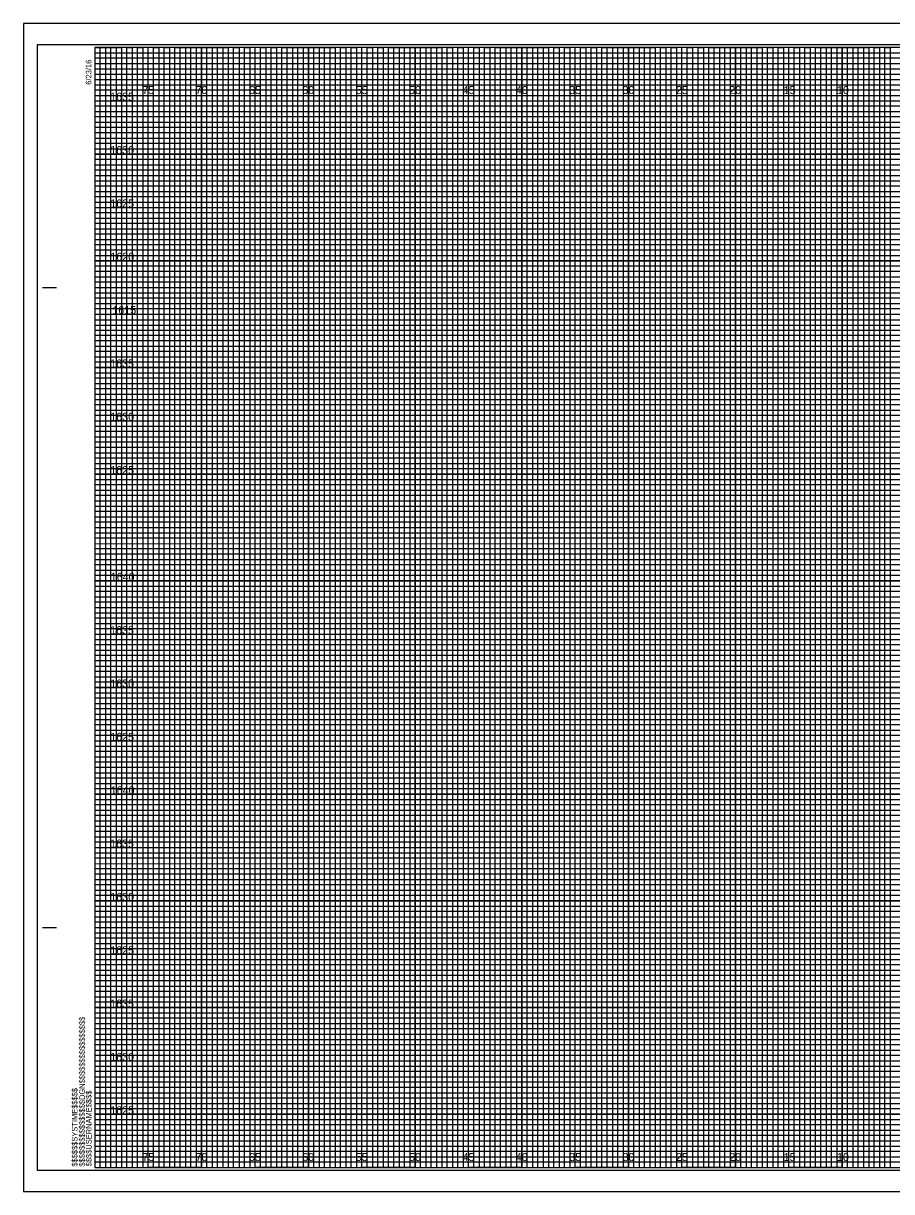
# Model space of a CAD drawing. Extents: x -7 to 162, y -2 to 107.
# Drawn here: x -6.7 to 74.6, y -2.3 to 107.3 of the extents above; entities that cross this region are included whole.
import ezdxf

# ---------------------------------------------------------------- set-up
doc = ezdxf.new("R2010")
doc.units = 0
for name, color, linetype in [('Prop XS Elevation Labels', 7, 'Continuous'), ('Prop XS Offset Labels', 7, 'Continuous'), ('Sheet Cross Section CELL', 7, 'Continuous'), ('Sheet Cross Section Grid Major CELL', 7, 'Continuous'), ('Sheet Cross Section Grid Middle CELL', 7, 'Continuous'), ('Sheet Cross Section Grid Minor 1 CELL', 7, 'Continuous'), ('Sheet Cross Section Grid Minor 2 CELL', 7, 'Continuous'), ('Sheet Cutting Line CELL', 7, 'Continuous'), ('Sheet DOT Grid CELL', 7, 'Continuous'), ('Sheet Plot Border Inside CELL', 7, 'Continuous'), ('Sheet Plot Border Outside CELL', 7, 'Continuous')]:
    doc.layers.add(name, color=color, linetype=linetype)

msp = doc.modelspace()

# ---------------------------------------------------------------- linework, layer by layer
at = {"layer": 'Sheet Cross Section CELL'}
for p, q in [((-4.9, 82.5), (-3.65, 82.5)), ((-4.85, 82.5), (-3.6, 82.5)), ((-4.9, 22.5), (-3.65, 22.5)), ((-4.85, 22.5), (-3.6, 22.5)), ((0, 0), (0, 0)), ((0, 0), (0, 0)), ((0, 0), (0, 0)), ((0, 0), (0, 0)), ((0, 0), (0, 0)), ((0, 0), (0, 0)), ((0, 0), (0, 0))]:
    msp.add_line(p, q, dxfattribs=at)
msp.add_lwpolyline([(160, 105), (0, 105), (0, 0), (160, 0)], close=True, dxfattribs=at)
at = {"layer": 'Sheet Cross Section Grid Major CELL'}
for p, q in [((5, 105), (0, 105)), ((5, 0), (5, 105)), ((15, 105), (10, 105)), ((10, 105), (10, 0)), ((15, 0), (15, 105)), ((25, 105), (20, 105)), ((20, 105), (20, 0)), ((25, 0), (25, 105)), ((35, 105), (30, 105)), ((30, 105), (30, 0)), ((35, 0), (35, 105)), ((45, 105), (40, 105)), ((40, 105), (40, 0)), ((45, 0), (45, 105)), ((55, 105), (50, 105)), ((50, 105), (50, 0)), ((55, 0), (55, 105)), ((65, 105), (60, 105)), ((60, 105), (60, 0)), ((65, 0), (65, 105)), ((75, 105), (70, 105)), ((70, 105), (70, 0)), ((10, 0), (5, 0)), ((20, 0), (15, 0)), ((30, 0), (25, 0)), ((40, 0), (35, 0)), ((50, 0), (45, 0)), ((60, 0), (55, 0)), ((70, 0), (65, 0))]:
    msp.add_line(p, q, dxfattribs=at)
for points in [[(0, 100), (160, 100), (160, 95), (0, 95)], [(0, 90), (160, 90), (160, 85), (0, 85)], [(0, 80), (160, 80), (160, 75), (0, 75)], [(0, 70), (160, 70), (160, 65), (0, 65)], [(0, 60), (160, 60), (160, 55), (0, 55)], [(0, 50), (160, 50), (160, 45), (0, 45)], [(0, 40), (160, 40), (160, 35), (0, 35)], [(0, 30), (160, 30), (160, 25), (0, 25)], [(0, 20), (160, 20), (160, 15), (0, 15)], [(0, 10), (160, 10), (160, 5), (0, 5)]]:
    msp.add_lwpolyline(points, dxfattribs=at)
at = {"layer": 'Sheet Cross Section Grid Middle CELL'}
for points in [[(0, 105), (2.5, 105), (2.5, 0), (7.5, 0), (7.5, 105), (12.5, 105), (12.5, 0), (17.5, 0), (17.5, 105), (22.5, 105), (22.5, 0), (27.5, 0), (27.5, 105), (32.5, 105), (32.5, 0), (37.5, 0), (37.5, 105), (42.5, 105), (42.5, 0), (47.5, 0), (47.5, 105), (52.5, 105), (52.5, 0), (57.5, 0), (57.5, 105), (62.5, 105), (62.5, 0), (67.5, 0), (67.5, 105), (72.5, 105), (72.5, 0), (77.5, 0)], [(0, 102.5), (137.5, 102.5)], [(0, 92.5), (160, 92.5), (160, 97.5), (0, 97.5)], [(0, 82.5), (160, 82.5), (160, 87.5), (0, 87.5)], [(0, 72.5), (160, 72.5), (160, 77.5), (0, 77.5)], [(0, 62.5), (160, 62.5), (160, 67.5), (0, 67.5)], [(0, 52.5), (160, 52.5), (160, 57.5), (0, 57.5)], [(0, 42.5), (160, 42.5), (160, 47.5), (0, 47.5)], [(0, 32.5), (160, 32.5), (160, 37.5), (0, 37.5)], [(0, 22.5), (160, 22.5), (160, 27.5), (0, 27.5)], [(0, 12.5), (160, 12.5), (160, 17.5), (0, 17.5)], [(0, 2.5), (160, 2.5), (160, 7.5), (0, 7.5)]]:
    msp.add_lwpolyline(points, dxfattribs=at)
at = {"layer": 'Sheet Cross Section Grid Minor 1 CELL'}
for p, q in [((0, 104.5), (130, 104.5)), ((130, 103.99), (0, 103.99)), ((0, 103.99), (0, 103.5)), ((0, 103.5), (130, 103.5)), ((130, 102.95), (0, 102.95)), ((0, 102.95), (0, 102)), ((0, 102), (160, 102))]:
    msp.add_line(p, q, dxfattribs=at)
for points in [[(0, 101.5), (135, 101.5), (160, 101.5), (160, 101), (0, 101)], [(0, 100.5), (160, 100.5), (160, 99.5), (0, 99.5)], [(0, 99), (160, 99), (160, 98.5), (0, 98.49)], [(0, 98), (160, 98), (160, 97), (0, 97)], [(0, 96.5), (160, 96.5), (160, 96), (0, 96)], [(0, 95.5), (160, 95.5), (160, 94.5), (0, 94.5)], [(0, 94), (160, 94), (160, 93.5), (0, 93.5)], [(0, 93), (160, 93), (160, 92), (0, 92)], [(0, 91.5), (160, 91.5), (160, 91), (0, 91)], [(0, 90.5), (160, 90.5), (160, 89.5), (0, 89.5)], [(0, 89), (160, 89), (160, 88.5), (0, 88.5)], [(0, 88), (160, 88), (160, 86.98), (160, 86.5), (160, 86), (0, 86)], [(0, 87), (160, 87), (160, 86.5), (0, 86.5)], [(0, 85.5), (160, 85.5), (160, 84.5), (0, 84.52)], [(0, 84.52), (160, 84.5), (160, 84), (0, 84)], [(0, 83.5), (160, 83.5), (160, 83), (0, 83)], [(0, 82), (160, 82), (160, 81.5), (0, 81.5)], [(0, 81), (160, 81), (160, 80.5), (0, 80.5)], [(-0.04, 79.45), (160, 79.45), (160, 78.94), (-0.04, 78.94)], [(0, 78.5), (160, 78.5), (160, 78), (0, 78)], [(0, 77), (160, 77), (160, 76.5), (0, 76.5)], [(0, 76), (160, 76), (160, 75.5), (0, 75.5)], [(0, 74.5), (160, 74.5), (160, 74), (0, 74)], [(0, 73.5), (160, 73.5), (160, 73), (0, 73)], [(0, 72), (160, 72), (160, 71.5), (0, 71.5)], [(0, 71), (160, 71), (160, 70.5), (0, 70.5)], [(0, 69.5), (160, 69.5), (160, 68.99), (0, 69)], [(0, 68.5), (160, 68.5), (160, 68), (0, 68)], [(0, 67), (160, 67), (160, 66.5), (0, 66.5)], [(0, 66), (160, 66), (160, 65.5), (0, 65.5)], [(0, 64.5), (160, 64.5), (160, 64), (0, 64)], [(0, 63.5), (160, 63.5), (160, 63), (0, 63)], [(0, 62), (160, 62), (160, 61.5), (0, 61.5)], [(0, 61), (160, 61), (160, 60.5), (0, 60.5)], [(0, 59.5), (160, 59.5), (160, 59), (0, 59)], [(0, 58.5), (160.03, 58.45), (160, 58), (0, 58)], [(0, 57), (160, 57), (160, 56.5), (0, 56.5)], [(0, 56), (160, 56), (160, 55.5), (0, 55.5)], [(0, 54.5), (160, 54.5), (160, 54), (0, 54)], [(0, 53.5), (160, 53.5), (160, 53), (0, 53)], [(0, 52), (160, 52), (160, 51.5), (0, 51.5)], [(0, 51), (160, 51), (160, 50.5), (0, 50.5)], [(0, 49.5), (160, 49.5), (160, 49), (0, 49)], [(0, 48.5), (160, 48.5), (160, 48), (0, 48)], [(0, 47), (160, 47), (160, 46.5), (0, 46.5)], [(0, 46), (160, 46), (160, 45.5), (0, 45.5)], [(0, 44.5), (160, 44.5), (160, 44), (0, 44)], [(0, 43.5), (160, 43.5), (160, 43), (0, 43)], [(0, 42), (160, 42), (160, 41.5), (0, 41.5)], [(0, 41), (160, 41), (160, 40.5), (0, 40.5)], [(0, 39.5), (160, 39.5), (160, 38.99), (0, 39)], [(0, 38.5), (160, 38.5), (160, 38), (0, 38)], [(0, 37), (160, 37), (160, 36.5), (0, 36.5)], [(0, 36), (160, 36), (160, 35.5), (0, 35.5)], [(0, 34.5), (160, 34.5), (160, 34), (0, 34)], [(0, 33.5), (160, 33.5), (160, 33), (0, 33)], [(0, 32), (160, 32), (160, 31.5), (0, 31.5)], [(0, 31), (160, 31), (160, 30.5), (0, 30.5)], [(0, 29.5), (160, 29.5), (160, 29), (0, 29)], [(0, 28.5), (160.03, 28.46), (160, 28), (0, 28)], [(0, 27), (160, 27), (160, 26.5), (0, 26.5)], [(0, 26), (160, 26), (160, 25.5), (0, 25.5)], [(0, 24.5), (160, 24.5), (160, 24), (0, 24)], [(0, 23.5), (160, 23.5), (160, 23), (0, 23)], [(0, 22), (160, 22), (160, 21.5), (0, 21.5)], [(0, 21), (160, 21), (160, 20.5), (0, 20.5)], [(0, 19.5), (160, 19.5), (160, 19), (0, 19)], [(0, 18.5), (160, 18.5), (160, 18), (0, 18)], [(0, 17), (160, 17), (160, 16.5), (0, 16.5)], [(0, 16), (160, 16), (160, 15.5), (0, 15.5)], [(0, 14.5), (160, 14.5), (160, 14), (0, 14)], [(0, 13.5), (160, 13.5), (160, 13), (0, 13)], [(0, 12), (160, 12), (160, 11.5), (0, 11.5)], [(0, 11), (160, 11), (160, 10.5), (0, 10.5)], [(0, 9.5), (160, 9.5), (160, 9), (0, 9)], [(0, 8.5), (160, 8.5), (160, 8), (0, 8)], [(0, 7), (160, 7), (160, 6.5), (0, 6.5)], [(0, 6), (160, 6), (160, 5.5), (0, 5.5)], [(0, 4.5), (160, 4.5), (160, 4), (0, 4)], [(0, 3.5), (160, 3.5), (160, 3), (0, 3)], [(0, 2), (160, 2), (160, 1.5), (0, 1.5)], [(0, 1), (160, 1), (160, 0.5), (0, 0.5)]]:
    msp.add_lwpolyline(points, dxfattribs=at)
at = {"layer": 'Sheet Cross Section Grid Minor 2 CELL'}
for points in [[(0, 0), (0.5, 0), (0.5, 105), (1, 105), (1, 0)], [(1, 0), (1.5, 0), (1.5, 105), (2, 105), (2, 0)], [(2.5, 0), (3, 0), (3, 105), (3.5, 105), (3.5, 0)], [(3.5, 0), (4, 0), (4, 105), (4.5, 105), (4.5, 0)], [(5, 0), (5.5, 0), (5.5, 105), (6, 105), (6, 0)], [(6, 0), (6.5, 0), (6.5, 105), (7, 105), (7, 0)], [(7.5, 0), (8, 0), (8, 105), (8.5, 105), (8.5, 0)], [(8.5, 0), (9, 0), (9, 105), (9.5, 105), (9.5, 0)], [(10, 0), (10.5, 0), (10.5, 105), (11, 105), (11, 0)], [(11, 0), (11.5, 0), (11.5, 105), (12, 105), (12, 0)], [(12.5, 0), (13, 0), (13, 105), (13.5, 105), (13.5, 0)], [(13.5, 0), (14, 0), (14, 105), (14.5, 105), (14.5, 0)], [(15, 0), (15.5, 0), (15.5, 105), (16, 105), (16, 0)], [(16, 0), (16.5, 0), (16.5, 105), (17, 105), (17, 0)], [(17.5, 0), (18, 0), (18, 105), (18.5, 105), (18.5, 0)], [(18.5, 0), (19, 0), (19, 105), (19.5, 105), (19.5, 0)], [(20, 0), (20.5, 0), (20.5, 105), (21, 105), (21, 0)], [(21, 0), (21.5, 0), (21.5, 105), (22, 105), (22, 0)], [(22.5, 0), (23, 0), (23, 105), (23.5, 105), (23.5, 0)], [(23.5, 0), (24, 0), (24, 105), (24.5, 105), (24.5, 0)], [(25, 0), (25.5, 0), (25.5, 105), (26, 105), (26, 0)], [(26, 0), (26.5, 0), (26.5, 105), (27, 105), (27, 0)], [(27.5, 0), (28, 0), (28, 105), (28.5, 105), (28.5, 0)], [(28.5, 0), (29, 0), (29, 105), (29.5, 105), (29.5, 0)], [(30, 0), (30.5, 0), (30.5, 105), (31, 105), (31, 0)], [(31, 0), (31.5, 0), (31.5, 105), (32, 105), (32, 0)], [(32.5, 0), (33, 0), (33, 105), (33.5, 105), (33.5, 0)], [(33.5, 0), (34, 0), (34, 105), (34.5, 105), (34.5, 0)], [(35, 0), (35.5, 0), (35.5, 105), (36, 105), (36, 0)], [(36, 0), (36.5, 0), (36.5, 105), (37, 105), (37, 0)], [(37.5, 0), (38, 0), (38, 105), (38.5, 105), (38.5, 0)], [(38.5, 0), (39, 0), (39, 105), (39.5, 105), (39.5, 0)], [(40, 0), (40.5, 0), (40.5, 105), (41, 105), (41, 0)], [(41, 0), (41.5, 0), (41.5, 105), (42, 105), (42, 0)], [(42.5, 0), (43, 0), (43, 105), (43.5, 105), (43.5, 0)], [(43.5, 0), (44, 0), (44, 105), (44.5, 105), (44.5, 0)], [(45, 0), (45.5, 0), (45.5, 105), (46, 105), (46, 0)], [(46, 0), (46.5, 0), (46.5, 105), (47, 105), (47, 0)], [(47.5, 0), (48, 0), (48, 105), (48.5, 105), (48.5, 0)], [(48.5, 0), (49, 0), (49, 105), (49.5, 105), (49.5, 0)], [(50, 0), (50.5, 0), (50.5, 105), (51, 105), (51, 0)], [(51, 0), (51.5, 0), (51.5, 105), (52, 105), (52, 0)], [(52.5, 0), (53, 0), (53, 105), (53.5, 105), (53.5, 0)], [(53.5, 0), (54, 0), (54, 105), (54.5, 105), (54.5, 0)], [(55, 0), (55.5, 0), (55.5, 105), (56, 105), (56, 0)], [(56, 0), (56.5, 0), (56.5, 105), (57, 105), (57, 0)], [(57.5, 0), (58, 0), (58, 105), (58.5, 105), (58.5, 0)], [(58.5, 0), (59, 0), (59, 105), (59.5, 105), (59.5, 0)], [(60, 0), (60.5, 0), (60.5, 105), (61, 105), (61, 0)], [(61, 0), (61.5, 0), (61.5, 105), (62, 105), (62, 0)], [(62.5, 0), (63, 0), (63, 105), (63.5, 105), (63.5, 0)], [(63.5, 0), (64, 0), (64, 105), (64.5, 105), (64.5, 0)], [(65, 0), (65.5, 0), (65.5, 105), (66, 105), (66, 0)], [(66, 0), (66.5, 0), (66.5, 105), (67, 105), (67, 0)], [(67.5, 0), (68, 0), (68, 105), (68.5, 105), (68.5, 0)], [(68.5, 0), (69, 0), (69, 105), (69.5, 105), (69.5, 0)], [(70, 0), (70.5, 0), (70.5, 105), (71, 105), (71, 0)], [(71, 0), (71.5, 0), (71.5, 105), (72, 105), (72, 0)], [(72.5, 0), (73, 0), (73, 105), (73.5, 105), (73.5, 0)], [(73.5, 0), (74, 0), (74, 105), (74.5, 105), (74.5, 0)]]:
    msp.add_lwpolyline(points, dxfattribs=at)
at = {"layer": 'Sheet Cutting Line CELL'}
for p, q in [((161.65, 107.25), (-6.7, 107.25)), ((-6.7, 107.25), (-6.7, -2.25)), ((-6.7, -2.25), (161.65, -2.25))]:
    msp.add_line(p, q, dxfattribs=at)
at = {"layer": 'Sheet DOT Grid CELL'}
for p, q in [((5, 0), (5, 105)), ((10, 0), (10, 105)), ((15, 0), (15, 105)), ((20, 0), (20, 105)), ((25, 0), (25, 105)), ((30, 0), (30, 105)), ((35, 0), (35, 105)), ((40, 0), (40, 105)), ((45, 0), (45, 105)), ((50, 0), (50, 105)), ((55, 0), (55, 105)), ((60, 0), (60, 105)), ((65, 0), (65, 105)), ((70, 0), (70, 105)), ((0, 100), (160, 100)), ((0, 95), (160, 95)), ((0, 90), (160, 90)), ((0, 85), (160, 85)), ((0, 80), (160, 80)), ((0, 75), (160, 75)), ((0, 70), (160, 70)), ((0, 65), (160, 65)), ((0, 60), (160, 60)), ((0, 55), (160, 55)), ((0, 50), (160, 50)), ((0, 45), (160, 45)), ((0, 40), (160, 40)), ((0, 35), (160, 35)), ((0, 30), (160, 30)), ((0, 25), (160, 25)), ((0, 20), (160, 20)), ((0, 15), (160, 15)), ((0, 10), (160, 10)), ((0, 5), (160, 5))]:
    msp.add_line(p, q, dxfattribs=at)
at = {"layer": 'Sheet Plot Border Inside CELL'}
msp.add_lwpolyline([(-5.4, -0.25), (161.2, -0.25), (161.2, 105.25), (-5.4, 105.25)], close=True, dxfattribs=at)
at = {"layer": 'Sheet Plot Border Outside CELL'}
msp.add_lwpolyline([(-6.7, -2.25), (161.65, -2.25), (161.65, 107.25), (-6.7, 107.25)], close=True, dxfattribs=at)

# ---------------------------------------------------------------- texts
at = {"layer": 'Prop XS Elevation Labels'}
for s, p in [('1635', (1.43, 100)), ('1630', (1.44, 95)), ('1625', (1.44, 90)), ('1620', (1.45, 85)), ('1615', (1.63, 80)), ('1635', (1.43, 75)), ('1630', (1.44, 70)), ('1625', (1.44, 65)), ('1640', (1.48, 55)), ('1635', (1.43, 50)), ('1630', (1.44, 45)), ('1625', (1.44, 40)), ('1640', (1.48, 35)), ('1635', (1.43, 30)), ('1630', (1.44, 25)), ('1625', (1.44, 20)), ('1635', (1.43, 15)), ('1630', (1.44, 10)), ('1625', (1.44, 5))]:
    msp.add_text(s, height=0.75, dxfattribs=at).set_placement(p)
at = {"layer": 'Prop XS Offset Labels'}
for s, p in [('75', (4.44, 100.62)), ('70', (9.43, 100.62)), ('65', (14.44, 100.62)), ('60', (19.43, 100.62)), ('55', (24.44, 100.62)), ('50', (29.43, 100.62)), ('45', (34.44, 100.62)), ('40', (39.43, 100.62)), ('35', (44.44, 100.62)), ('30', (49.43, 100.62)), ('25', (54.44, 100.62)), ('20', (59.43, 100.62)), ('15', (64.53, 100.62)), ('10', (69.52, 100.62)), ('75', (4.44, 0.62)), ('70', (9.43, 0.62)), ('65', (14.44, 0.62)), ('60', (19.43, 0.62)), ('55', (24.44, 0.62)), ('50', (29.43, 0.62)), ('45', (34.44, 0.62)), ('40', (39.43, 0.62)), ('35', (44.44, 0.62)), ('30', (49.43, 0.62)), ('25', (54.44, 0.62)), ('20', (59.43, 0.62)), ('15', (64.53, 0.62)), ('10', (69.52, 0.62))]:
    msp.add_text(s, height=0.75, dxfattribs=at).set_placement(p)
at = {"layer": 'Sheet Cross Section CELL'}
for s, p in [('6/23/16', (-0.33, 101.5)), ('$$$$$$$$$$$$$$$$DGN$$$$$$$$$$$$$$$$', (-0.94, 0.09)), ('$$$$$$SYSTIME$$$$$', (-1.63, 0.09)), ('$$$$USERNAME$$$$', (-0.31, 0.12))]:
    msp.add_text(s, height=0.525, rotation=90, dxfattribs=at).set_placement(p)

doc.saveas('drawing.dxf')
